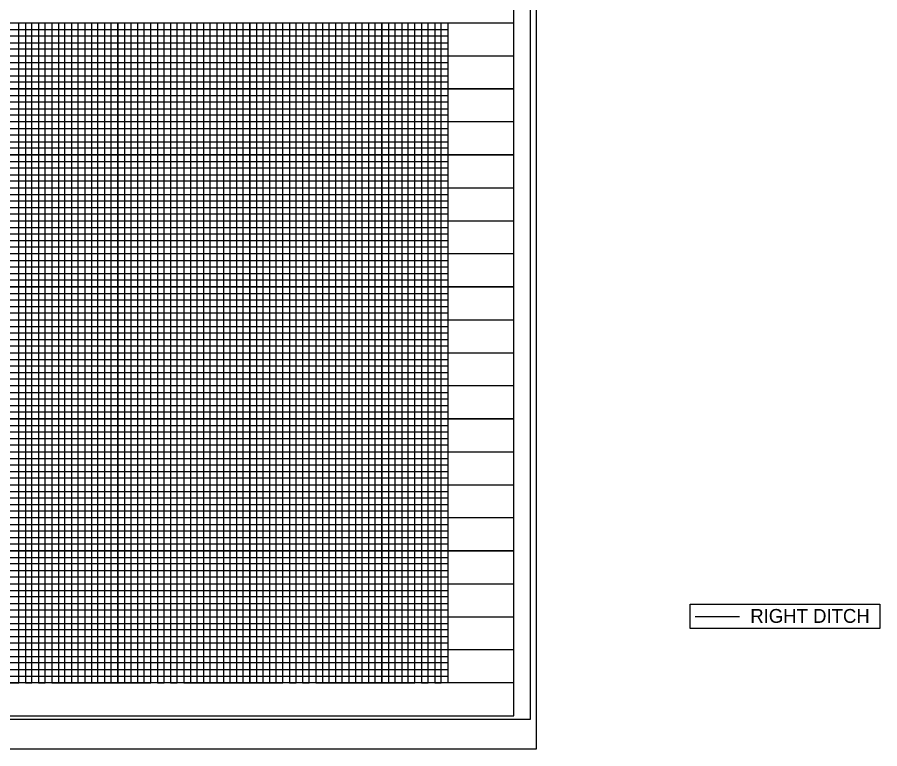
# Model space of a CAD drawing. Extents: x 1810963 to 1812934, y 722070 to 723170.
# Drawn here: x 1812254 to 1812908, y 722070 to 722624 of the extents above; entities that cross this region are included whole.
import ezdxf

# ---------------------------------------------------------------- set-up
doc = ezdxf.new("R2010")
doc.units = 0
for name, color, linetype in [('Exist Horizontal Alignment Tick Label', 7, 'Continuous'), ('Old_Level_11', 7, 'Continuous'), ('Old_Level_2', 7, 'Continuous'), ('Prop Conc 2ft 6in Curb and Gutter', 7, 'Continuous'), ('Prop PFL VPI Symbol CELL', 7, 'Continuous'), ('Prop RDY Traffic Signal CELL', 7, 'Continuous'), ('Prop Shade Heavy', 7, 'Continuous'), ('Prop Shade Light', 7, 'Continuous'), ('Prop Vertical Profile Ditch Grade Right', 7, 'Continuous'), ('Sheet North Arrow CELL', 7, 'Continuous'), ('Sheet Symbology CELL', 7, 'Continuous'), ('Sheet Title CELL', 7, 'Continuous')]:
    doc.layers.add(name, color=color, linetype=linetype)

msp = doc.modelspace()

# ---------------------------------------------------------------- linework, layer by layer
at = {"layer": 'Old_Level_11'}
msp.add_lwpolyline([(1810976.46, 722092.33), (1812642.96, 722092.33), (1812642.96, 723147.43), (1810976.46, 723147.43)], close=True, dxfattribs=at)
at = {"layer": 'Old_Level_2'}
msp.add_lwpolyline([(1812763.88, 722179.51), (1812907.55, 722179.51), (1812907.55, 722161.02), (1812763.88, 722161.02)], close=True, dxfattribs=at)
at = {"layer": 'Prop Conc 2ft 6in Curb and Gutter'}
for p, q in [((1811130.46, 722619.88), (1812630.35, 722619.88)), ((1812280.46, 722619.88), (1812280.46, 722119.88)), ((1812330.46, 722619.88), (1812330.46, 722119.88)), ((1812380.46, 722619.88), (1812380.46, 722119.88)), ((1812430.46, 722619.88), (1812430.46, 722119.88)), ((1812480.46, 722619.88), (1812480.46, 722119.88)), ((1812530.46, 722619.88), (1812530.46, 722119.88)), ((1812580.46, 722619.88), (1812580.46, 722119.88)), ((1811130.46, 722569.88), (1812630.35, 722569.88)), ((1811130.46, 722519.88), (1812630.35, 722519.88)), ((1811130.46, 722469.88), (1812630.35, 722469.88)), ((1811130.46, 722419.88), (1812630.35, 722419.88)), ((1811130.46, 722369.88), (1812630.35, 722369.88)), ((1811130.46, 722319.88), (1812630.35, 722319.88)), ((1811130.46, 722269.88), (1812630.35, 722269.88)), ((1811130.46, 722219.88), (1812630.35, 722219.88)), ((1811130.46, 722169.88), (1812630.35, 722169.88))]:
    msp.add_line(p, q, dxfattribs=at)
at = {"layer": 'Prop PFL VPI Symbol CELL'}
msp.add_lwpolyline([(1811180.46, 722619.88), (1812580.46, 722619.88), (1812580.46, 722119.88), (1811180.46, 722119.88)], close=True, dxfattribs=at)
at = {"layer": 'Prop RDY Traffic Signal CELL'}
msp.add_line((1810963.46, 722069.88), (1812647.46, 722069.88), dxfattribs=at)
at = {"layer": 'Prop Shade Heavy'}
for p, q in [((1812230.46, 722619.88), (1812280.46, 722619.88)), ((1812330.46, 722619.88), (1812380.46, 722619.88)), ((1812430.46, 722619.88), (1812480.46, 722619.88)), ((1812530.46, 722619.88), (1812580.46, 722619.88)), ((1812530.46, 722119.88), (1812530.46, 722119.88))]:
    msp.add_line(p, q, dxfattribs=at)
for points in [[(1812230.46, 722619.88), (1812280.46, 722619.88), (1812280.46, 722119.88), (1812330.46, 722119.88), (1812330.46, 722619.88), (1812380.46, 722619.88), (1812380.46, 722119.88), (1812430.46, 722119.88), (1812430.46, 722619.88), (1812480.46, 722619.88), (1812480.46, 722119.88), (1812530.46, 722119.88), (1812530.46, 722119.88), (1812530.46, 722619.88), (1812580.46, 722619.88), (1812580.46, 722119.88)], [(1812630.46, 722569.88), (1811130.46, 722569.88)], [(1812630.46, 722519.88), (1811130.46, 722519.88), (1811130.46, 722469.88), (1812630.46, 722469.88)], [(1812630.46, 722419.88), (1811130.46, 722419.88), (1811130.46, 722369.88), (1812630.46, 722369.88)], [(1812630.46, 722319.88), (1811130.46, 722319.88), (1811130.46, 722269.88), (1812630.46, 722269.88)], [(1812630.46, 722219.88), (1811130.46, 722219.88), (1811130.46, 722219.88), (1811130.46, 722169.88), (1812630.46, 722169.88)], [(1812630.46, 722119.88), (1811130.46, 722119.88)]]:
    msp.add_lwpolyline(points, dxfattribs=at)
at = {"layer": 'Prop Shade Light'}
for points in [[(1812205.46, 722119.88), (1812255.46, 722119.88), (1812255.46, 722619.88), (1812305.46, 722619.88), (1812305.46, 722119.88), (1812355.46, 722119.88), (1812355.46, 722619.88), (1812405.46, 722619.88), (1812405.46, 722119.88), (1812455.46, 722119.88), (1812455.46, 722619.88), (1812505.46, 722619.88), (1812505.46, 722119.88), (1812555.46, 722119.88), (1812555.46, 722619.88)], [(1811130.46, 722594.88), (1812630.46, 722594.88)], [(1812630.46, 722544.88), (1811130.46, 722544.88), (1811130.46, 722494.88), (1812630.46, 722494.88)], [(1812630.46, 722444.88), (1811130.46, 722444.88), (1811130.46, 722394.88), (1812630.46, 722394.88)], [(1812630.46, 722344.88), (1811130.46, 722344.88), (1811130.46, 722294.88), (1812630.46, 722294.88)], [(1812630.46, 722244.88), (1811130.46, 722244.88), (1811130.46, 722194.88), (1812630.46, 722194.88)], [(1812630.46, 722144.88), (1811130.46, 722144.88)]]:
    msp.add_lwpolyline(points, dxfattribs=at)
at = {"layer": 'Prop Vertical Profile Ditch Grade Right'}
msp.add_line((1812767.79, 722170.2), (1812801.44, 722170.2), dxfattribs=at)
at = {"layer": 'Sheet North Arrow CELL'}
msp.add_lwpolyline([(1810963.46, 722069.88), (1812647.46, 722069.88), (1812647.46, 723169.88), (1810963.46, 723169.88)], close=True, dxfattribs=at)
at = {"layer": 'Sheet Symbology CELL'}
for p, q in [((1811130.46, 722619.88), (1812630.46, 722619.88)), ((1812630.46, 722119.88), (1811130.46, 722119.88)), ((1811130.46, 722094.88), (1812630.46, 722094.88))]:
    msp.add_line(p, q, dxfattribs=at)
msp.add_lwpolyline([(1812630.46, 723144.88), (1811130.46, 723144.88), (1811130.46, 722094.88), (1812630.46, 722094.88)], close=True, dxfattribs=at)
at = {"layer": 'Sheet Title CELL'}
for p, q in [((1811180.46, 722614.88), (1812580.46, 722614.88)), ((1812580.46, 722609.88), (1811180.46, 722609.88)), ((1811180.46, 722604.88), (1812580.46, 722604.88)), ((1812580.46, 722599.88), (1811180.46, 722599.88)), ((1811180.46, 722589.88), (1812580.46, 722589.88)), ((1812580.46, 722584.88), (1811180.46, 722584.88)), ((1811180.46, 722579.88), (1812580.46, 722579.88)), ((1812580.46, 722574.88), (1811180.46, 722574.88)), ((1811180.46, 722564.88), (1812580.46, 722564.88)), ((1812580.46, 722559.88), (1811180.46, 722559.88)), ((1811180.46, 722554.88), (1812580.46, 722554.88)), ((1812580.46, 722549.88), (1811180.46, 722549.88)), ((1811180.46, 722539.88), (1812580.46, 722539.88)), ((1812580.46, 722534.88), (1811180.46, 722534.88)), ((1811180.46, 722529.88), (1812580.46, 722529.88)), ((1812580.46, 722524.88), (1811180.46, 722524.88)), ((1811180.46, 722514.88), (1812580.46, 722514.88)), ((1812580.46, 722509.88), (1811180.46, 722509.88)), ((1811180.46, 722504.88), (1812580.46, 722504.88)), ((1812580.46, 722499.88), (1811180.46, 722499.88)), ((1811180.46, 722489.88), (1812580.46, 722489.88)), ((1812580.46, 722484.88), (1811180.46, 722484.88)), ((1811180.46, 722479.88), (1812580.46, 722479.88)), ((1812580.46, 722474.88), (1811180.46, 722474.88)), ((1811180.46, 722464.88), (1812580.46, 722464.88)), ((1812580.46, 722459.88), (1811180.46, 722459.88)), ((1811180.46, 722454.88), (1812580.46, 722454.88)), ((1812580.46, 722449.88), (1811180.46, 722449.88)), ((1811180.46, 722439.88), (1812580.46, 722439.88)), ((1812580.46, 722434.88), (1811180.46, 722434.88)), ((1811180.46, 722429.88), (1812580.46, 722429.88)), ((1812580.46, 722424.88), (1811180.46, 722425.03)), ((1811180.46, 722414.88), (1812580.46, 722414.88)), ((1812580.46, 722409.88), (1811180.46, 722409.88)), ((1811180.46, 722404.88), (1812580.46, 722404.88)), ((1812580.46, 722399.88), (1811180.46, 722399.88)), ((1811180.46, 722389.88), (1812580.46, 722389.88)), ((1812580.46, 722384.88), (1811180.46, 722384.88)), ((1811180.46, 722379.88), (1812580.46, 722379.88)), ((1812580.46, 722374.88), (1811180.46, 722374.88)), ((1811180.46, 722364.88), (1812580.46, 722364.88)), ((1812580.46, 722359.88), (1811180.46, 722359.88)), ((1811180.46, 722354.88), (1812580.46, 722354.88)), ((1812580.46, 722349.88), (1811180.46, 722349.88)), ((1811180.46, 722339.88), (1812580.46, 722339.88)), ((1812580.46, 722334.88), (1811180.46, 722334.88)), ((1811180.46, 722329.88), (1812580.46, 722329.88)), ((1812580.46, 722324.88), (1811180.46, 722324.88)), ((1811180.46, 722314.88), (1812580.46, 722314.88)), ((1812580.46, 722309.88), (1811180.46, 722309.88)), ((1811180.46, 722304.88), (1812580.46, 722304.88)), ((1812580.46, 722299.88), (1811180.46, 722299.88)), ((1811180.46, 722289.88), (1812580.46, 722289.88)), ((1812580.46, 722284.88), (1811180.46, 722284.88)), ((1811180.46, 722279.88), (1812580.46, 722279.88)), ((1812580.46, 722274.88), (1811180.46, 722274.88)), ((1811180.46, 722264.88), (1812580.46, 722264.88)), ((1812580.46, 722259.88), (1811180.46, 722259.88)), ((1811180.46, 722254.88), (1812580.46, 722254.88)), ((1812580.46, 722249.88), (1811180.46, 722249.88)), ((1811180.46, 722239.88), (1812580.46, 722239.88)), ((1812580.46, 722234.88), (1811180.46, 722234.88)), ((1811180.46, 722229.88), (1812580.46, 722229.88)), ((1812580.46, 722224.88), (1811180.46, 722224.88)), ((1811180.46, 722214.88), (1812580.46, 722214.88)), ((1812580.46, 722209.88), (1811180.46, 722209.88)), ((1811180.46, 722204.88), (1812580.46, 722204.88)), ((1812580.46, 722199.88), (1811180.46, 722199.88)), ((1811180.46, 722189.88), (1812580.46, 722189.88)), ((1812580.46, 722184.88), (1811180.46, 722184.88)), ((1811180.46, 722179.88), (1812580.46, 722179.88)), ((1812580.46, 722174.88), (1811180.46, 722174.88)), ((1811180.46, 722164.88), (1812580.46, 722164.88)), ((1812580.46, 722159.88), (1811180.46, 722159.88)), ((1811180.46, 722154.88), (1812580.46, 722154.88)), ((1812580.46, 722149.88), (1811180.46, 722149.88)), ((1811180.46, 722139.88), (1812580.46, 722139.88)), ((1812580.46, 722134.88), (1811180.46, 722134.88)), ((1811180.46, 722129.88), (1812580.46, 722129.88)), ((1811180.46, 722124.88), (1812580.46, 722124.88)), ((1812580.46, 722124.88), (1812580.46, 722124.88))]:
    msp.add_line(p, q, dxfattribs=at)
for points in [[(1812250.46, 722619.88), (1812260.46, 722619.88), (1812260.46, 722119.88), (1812265.46, 722119.88), (1812265.46, 722619.88), (1812270.46, 722619.88), (1812270.46, 722119.88), (1812275.46, 722119.88), (1812275.46, 722619.88), (1812285.46, 722619.88), (1812285.46, 722119.88), (1812290.46, 722119.88), (1812290.46, 722619.88), (1812295.46, 722619.88), (1812295.46, 722119.88), (1812300.46, 722119.88), (1812300.46, 722619.88), (1812310.46, 722619.88), (1812310.46, 722119.88), (1812315.46, 722119.88), (1812315.46, 722619.88), (1812320.46, 722619.88), (1812320.46, 722119.88)], [(1812320.46, 722119.88), (1812325.46, 722119.88), (1812325.46, 722619.88), (1812335.46, 722619.88), (1812335.46, 722119.88), (1812340.46, 722119.88), (1812340.46, 722619.88), (1812345.46, 722619.88), (1812345.46, 722119.88), (1812350.46, 722119.88), (1812350.46, 722619.88), (1812360.46, 722619.88), (1812360.46, 722119.88), (1812365.46, 722119.88), (1812365.46, 722619.88), (1812370.46, 722619.88), (1812370.46, 722119.88), (1812375.46, 722119.88), (1812375.46, 722619.88), (1812385.46, 722619.88), (1812385.46, 722119.88), (1812390.46, 722119.88), (1812390.46, 722619.88), (1812395.46, 722619.88), (1812395.46, 722119.88), (1812400.46, 722119.88), (1812400.46, 722619.88), (1812410.46, 722619.88), (1812410.46, 722119.88), (1812415.46, 722119.88), (1812415.46, 722619.88), (1812420.46, 722619.88), (1812420.46, 722119.88), (1812425.46, 722119.88), (1812425.46, 722619.88), (1812435.46, 722619.88), (1812435.46, 722119.88), (1812440.46, 722119.88), (1812440.46, 722619.88), (1812445.46, 722619.88), (1812445.46, 722119.88), (1812450.46, 722119.88), (1812450.46, 722619.88), (1812460.46, 722619.88), (1812460.46, 722119.88), (1812465.46, 722119.88), (1812465.46, 722619.88), (1812470.46, 722619.88), (1812470.46, 722119.88), (1812475.46, 722119.88), (1812475.46, 722619.88), (1812485.46, 722619.88), (1812485.46, 722119.88), (1812490.46, 722119.88), (1812490.46, 722619.88), (1812495.46, 722619.88), (1812495.46, 722119.88), (1812500.46, 722119.88), (1812500.46, 722619.88), (1812510.46, 722619.88), (1812510.46, 722119.88), (1812515.46, 722119.88), (1812515.46, 722619.88), (1812520.46, 722619.88), (1812520.46, 722119.88), (1812525.46, 722119.88), (1812525.46, 722619.88), (1812535.46, 722619.88), (1812535.46, 722119.88), (1812540.46, 722119.88), (1812540.46, 722619.88), (1812545.46, 722619.88), (1812545.46, 722119.88), (1812550.46, 722119.88), (1812550.46, 722619.88), (1812560.46, 722619.88), (1812560.46, 722119.88), (1812565.46, 722119.88), (1812565.46, 722619.88), (1812570.46, 722619.88), (1812570.46, 722119.88), (1812575.46, 722119.88), (1812575.46, 722619.88), (1812580.46, 722619.88)]]:
    msp.add_lwpolyline(points, dxfattribs=at)

# ---------------------------------------------------------------- texts
at = {"layer": 'Exist Horizontal Alignment Tick Label'}
msp.add_text('RIGHT DITCH', height=10.5, rotation=360, dxfattribs=at).set_placement((1812809.48, 722165.27))

doc.saveas('drawing.dxf')
